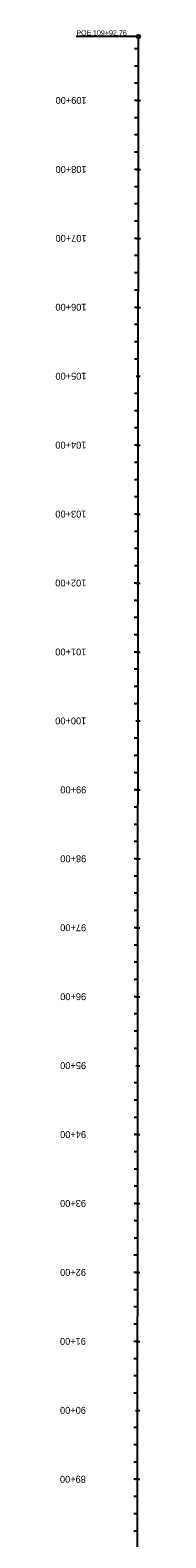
# Model space of a CAD drawing. Extents: x 11526371 to 11527168, y 9590726 to 9599509.
# Drawn here: x 11526424 to 11526547, y 9597322 to 9599509 of the extents above; entities that cross this region are included whole.
import ezdxf

# ---------------------------------------------------------------- set-up
doc = ezdxf.new("R2010")
doc.units = 0
for name, color, linetype in [('Alignment', 7, 'Continuous'), ('TextAlignment', 7, 'Continuous'), ('TextAlignmentLrg', 7, 'Continuous'), ('TextAlignmentSml', 7, 'Continuous')]:
    doc.layers.add(name, color=color, linetype=linetype)

msp = doc.modelspace()

# ---------------------------------------------------------------- linework, layer by layer
at = {"layer": 'Alignment'}
msp.add_line((11526542.9, 9596688), (11526544.3, 9599499.3), dxfattribs=at)
at = {"layer": 'TextAlignment'}
for p in [(11526544.3, 9599499.3), (11526454.3, 9599499.3)]:
    msp.add_line(p, (11526454.3, 9599499.3), dxfattribs=at)
msp.add_circle((11526544.3, 9599499.3), 2.67, dxfattribs=at)
at = {"layer": 'TextAlignmentLrg'}
for p, q in [((11526544.3, 9599406.5), (11526538.8, 9599406.5)), ((11526544.2, 9599306.5), (11526538.8, 9599306.5)), ((11526544.2, 9599206.5), (11526538.7, 9599206.5)), ((11526544.1, 9599106.5), (11526538.6, 9599106.5)), ((11526541, 9599006.5), (11526547.1, 9599006.5)), ((11526544, 9598906.5), (11526538.5, 9598906.5)), ((11526544, 9598806.5), (11526538.5, 9598806.5)), ((11526543.9, 9598706.5), (11526538.4, 9598706.5)), ((11526543.9, 9598606.5), (11526538.4, 9598606.5)), ((11526540.7, 9598506.5), (11526546.9, 9598506.5)), ((11526543.7, 9598406.5), (11526538.3, 9598406.5)), ((11526543.7, 9598306.5), (11526538.2, 9598306.5)), ((11526543.6, 9598206.5), (11526538.2, 9598206.5)), ((11526543.6, 9598106.5), (11526538.1, 9598106.5)), ((11526540.5, 9598006.5), (11526546.6, 9598006.5)), ((11526543.5, 9597906.5), (11526538, 9597906.5)), ((11526543.4, 9597806.5), (11526538, 9597806.5)), ((11526543.4, 9597706.5), (11526537.9, 9597706.5)), ((11526543.3, 9597606.5), (11526537.9, 9597606.5)), ((11526540.2, 9597506.5), (11526546.3, 9597506.5)), ((11526543.2, 9597406.5), (11526537.8, 9597406.5))]:
    msp.add_line(p, q, dxfattribs=at)
at = {"layer": 'TextAlignmentSml'}
for p, q in [((11526544.3, 9599481.5), (11526538.8, 9599481.5)), ((11526544.3, 9599456.5), (11526538.8, 9599456.5)), ((11526544.3, 9599431.5), (11526538.8, 9599431.5)), ((11526541.2, 9599406.5), (11526547.3, 9599406.5)), ((11526544.2, 9599381.5), (11526538.8, 9599381.5)), ((11526544.2, 9599356.5), (11526538.8, 9599356.5)), ((11526544.2, 9599331.5), (11526538.8, 9599331.5)), ((11526541.2, 9599306.5), (11526547.3, 9599306.5)), ((11526544.2, 9599281.5), (11526538.7, 9599281.5)), ((11526544.2, 9599256.5), (11526538.7, 9599256.5)), ((11526544.2, 9599231.5), (11526538.7, 9599231.5)), ((11526541.1, 9599206.5), (11526547.2, 9599206.5)), ((11526544.1, 9599181.5), (11526538.7, 9599181.5)), ((11526544.1, 9599156.5), (11526538.7, 9599156.5)), ((11526544.1, 9599131.5), (11526538.7, 9599131.5)), ((11526541, 9599106.5), (11526547.2, 9599106.5)), ((11526544.1, 9599081.5), (11526538.6, 9599081.5)), ((11526544.1, 9599056.5), (11526538.6, 9599056.5)), ((11526544.1, 9599031.5), (11526538.6, 9599031.5)), ((11526541, 9599006.5), (11526547.1, 9599006.5)), ((11526544, 9598981.5), (11526538.6, 9598981.5)), ((11526544, 9598956.5), (11526538.6, 9598956.5)), ((11526544, 9598931.5), (11526538.6, 9598931.5)), ((11526540.9, 9598906.5), (11526547.1, 9598906.5)), ((11526544, 9598881.5), (11526538.5, 9598881.5)), ((11526544, 9598856.5), (11526538.5, 9598856.5)), ((11526544, 9598831.5), (11526538.5, 9598831.5)), ((11526540.9, 9598806.5), (11526547, 9598806.5)), ((11526543.9, 9598781.5), (11526538.5, 9598781.5)), ((11526543.9, 9598756.5), (11526538.5, 9598756.5)), ((11526543.9, 9598731.5), (11526538.5, 9598731.5)), ((11526540.8, 9598706.5), (11526547, 9598706.5)), ((11526543.9, 9598681.5), (11526538.4, 9598681.5)), ((11526543.9, 9598656.5), (11526538.4, 9598656.5)), ((11526543.9, 9598631.5), (11526538.4, 9598631.5)), ((11526540.8, 9598606.5), (11526546.9, 9598606.5)), ((11526543.8, 9598581.5), (11526538.4, 9598581.5)), ((11526543.8, 9598556.5), (11526538.4, 9598556.5)), ((11526543.8, 9598531.5), (11526538.4, 9598531.5)), ((11526540.7, 9598506.5), (11526546.9, 9598506.5)), ((11526543.8, 9598481.5), (11526538.3, 9598481.5)), ((11526543.8, 9598456.5), (11526538.3, 9598456.5)), ((11526543.8, 9598431.5), (11526538.3, 9598431.5)), ((11526540.7, 9598406.5), (11526546.8, 9598406.5)), ((11526543.7, 9598381.5), (11526538.3, 9598381.5)), ((11526543.7, 9598356.5), (11526538.3, 9598356.5)), ((11526543.7, 9598331.5), (11526538.2, 9598331.5)), ((11526540.6, 9598306.5), (11526546.8, 9598306.5)), ((11526543.7, 9598281.5), (11526538.2, 9598281.5)), ((11526543.7, 9598256.5), (11526538.2, 9598256.5)), ((11526543.7, 9598231.5), (11526538.2, 9598231.5)), ((11526540.6, 9598206.5), (11526546.7, 9598206.5)), ((11526543.6, 9598181.5), (11526538.2, 9598181.5)), ((11526543.6, 9598156.5), (11526538.2, 9598156.5)), ((11526543.6, 9598131.5), (11526538.1, 9598131.5)), ((11526540.5, 9598106.5), (11526546.7, 9598106.5)), ((11526543.6, 9598081.5), (11526538.1, 9598081.5)), ((11526543.6, 9598056.5), (11526538.1, 9598056.5)), ((11526543.6, 9598031.5), (11526538.1, 9598031.5)), ((11526540.5, 9598006.5), (11526546.6, 9598006.5)), ((11526543.5, 9597981.5), (11526538.1, 9597981.5)), ((11526543.5, 9597956.5), (11526538.1, 9597956.5)), ((11526543.5, 9597931.5), (11526538, 9597931.5)), ((11526540.4, 9597906.5), (11526546.6, 9597906.5)), ((11526543.5, 9597881.5), (11526538, 9597881.5)), ((11526543.5, 9597856.5), (11526538, 9597856.5)), ((11526543.5, 9597831.5), (11526538, 9597831.5)), ((11526540.4, 9597806.5), (11526546.5, 9597806.5)), ((11526543.4, 9597781.5), (11526538, 9597781.5)), ((11526543.4, 9597756.5), (11526538, 9597756.5)), ((11526543.4, 9597731.5), (11526537.9, 9597731.5)), ((11526540.3, 9597706.5), (11526546.4, 9597706.5)), ((11526543.4, 9597681.5), (11526537.9, 9597681.5)), ((11526543.4, 9597656.5), (11526537.9, 9597656.5)), ((11526543.3, 9597631.5), (11526537.9, 9597631.5)), ((11526540.3, 9597606.5), (11526546.4, 9597606.5)), ((11526543.3, 9597581.5), (11526537.9, 9597581.5)), ((11526543.3, 9597556.5), (11526537.9, 9597556.5)), ((11526543.3, 9597531.5), (11526537.8, 9597531.5)), ((11526540.2, 9597506.5), (11526546.3, 9597506.5)), ((11526543.3, 9597481.5), (11526537.8, 9597481.5)), ((11526543.3, 9597456.5), (11526537.8, 9597456.5)), ((11526543.2, 9597431.5), (11526537.8, 9597431.5)), ((11526540.2, 9597406.5), (11526546.3, 9597406.5)), ((11526543.2, 9597381.5), (11526537.8, 9597381.5)), ((11526543.2, 9597356.5), (11526537.7, 9597356.5)), ((11526543.2, 9597331.5), (11526537.7, 9597331.5))]:
    msp.add_line(p, q, dxfattribs=at)

# ---------------------------------------------------------------- texts
at = {"layer": 'TextAlignment'}
for s, p in [('POE ', (11526454.3, 9599501)), ('109+92.76', (11526478.4, 9599500.9))]:
    msp.add_text(s, height=7.5, rotation=359.9705, dxfattribs=at).set_placement(p)
at = {"layer": 'TextAlignmentLrg'}
for s, p in [('105+00', (11526469.1, 9599011.6)), ('100+00', (11526468.8, 9598511.6)), ('95+00', (11526468.5, 9598011.6)), ('90+00', (11526468.3, 9597511.6))]:
    msp.add_text(s, height=10.02, rotation=179.9705, dxfattribs=at).set_placement(p)
at = {"layer": 'TextAlignmentSml'}
for s, p in [('109+00', (11526469.3, 9599411.6)), ('108+00', (11526469.2, 9599311.6)), ('107+00', (11526469.2, 9599211.6)), ('106+00', (11526469.1, 9599111.6)), ('105+00', (11526469.1, 9599011.6)), ('104+00', (11526469, 9598911.6)), ('103+00', (11526469, 9598811.6)), ('102+00', (11526468.9, 9598711.6)), ('101+00', (11526468.9, 9598611.6)), ('100+00', (11526468.8, 9598511.6)), ('99+00', (11526468.8, 9598411.6)), ('98+00', (11526468.7, 9598311.6)), ('97+00', (11526468.6, 9598211.6)), ('96+00', (11526468.6, 9598111.6)), ('95+00', (11526468.5, 9598011.6)), ('94+00', (11526468.5, 9597911.6)), ('93+00', (11526468.4, 9597811.6)), ('92+00', (11526468.4, 9597711.6)), ('91+00', (11526468.3, 9597611.6)), ('90+00', (11526468.3, 9597511.6)), ('89+00', (11526468.2, 9597411.6))]:
    msp.add_text(s, height=10.02, rotation=179.9705, dxfattribs=at).set_placement(p)

doc.saveas('drawing.dxf')
